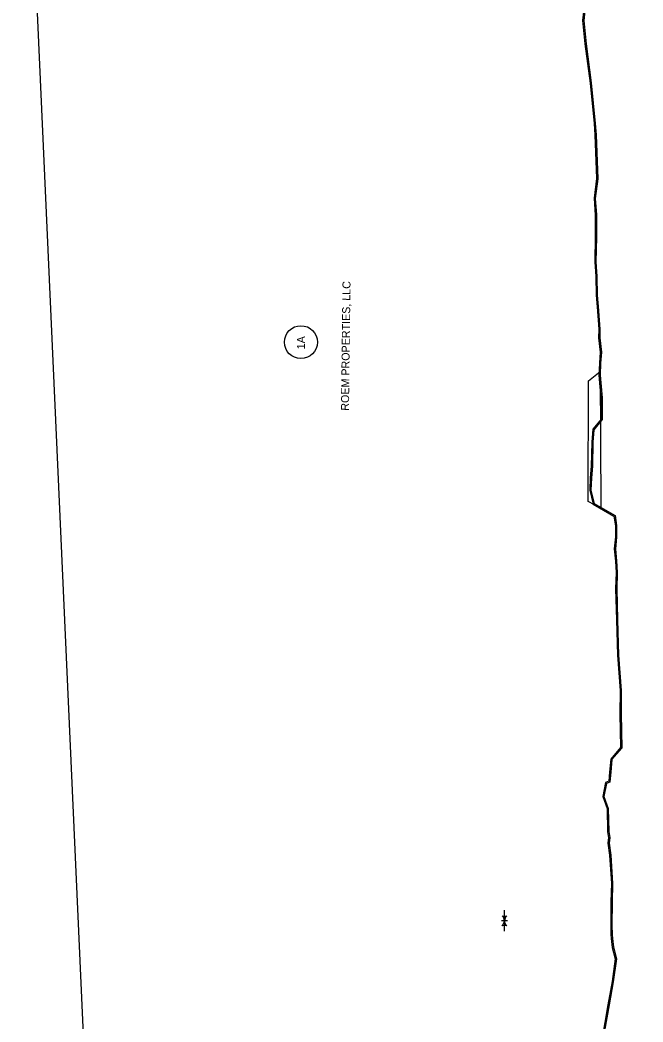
# Model space of a CAD drawing. Extents: x 20504422 to 20508365, y 7965199 to 7983597.
# Drawn here: x 20505551 to 20506611, y 7972359 to 7974062 of the extents above; entities that cross this region are included whole.
import ezdxf

# ---------------------------------------------------------------- set-up
doc = ezdxf.new("R2010")
doc.units = 0
for name, color, linetype in [('SurControl', 7, 'Continuous'), ('SurDikeDam', 7, 'Continuous'), ('SurLotCorner', 7, 'Continuous'), ('SurRipRap', 7, 'Continuous'), ('SurTopOfWater', 7, 'Continuous'), ('SurWetlands', 7, 'Continuous')]:
    doc.layers.add(name, color=color, linetype=linetype)

msp = doc.modelspace()

# ---------------------------------------------------------------- linework, layer by layer
at = {"layer": 'SurControl'}
msp.add_circle((20506029.1, 7973514.4), 28, dxfattribs=at)
at = {"layer": 'SurDikeDam'}
for p, q in [((20506518, 7973448.6), (20506537.8, 7973464.4)), ((20506537.8, 7973464.4), (20506539.1, 7973232.4)), ((20506517.4, 7973243.7), (20506518, 7973448.6)), ((20506539.1, 7973232.4), (20506517.4, 7973243.7))]:
    msp.add_line(p, q, dxfattribs=at)
at = {"layer": 'SurLotCorner'}
for p, q in [((20506375.1, 7972531.1), (20506375.3, 7972549)), ((20506380.2, 7972531), (20506370.1, 7972531.2)), ((20506375.1, 7972531.1), (20506374.9, 7972513.2))]:
    msp.add_line(p, q, dxfattribs=at)
for centre, radius, start, end in [((20506360.6, 7972529.7), 14.6, 5.3849, 43.1922), ((20506375.4, 7972550.3), 11.4, 248.6722, 289.8859), ((20506389.6, 7972529.4), 14.6, 135.366, 173.1732), ((20506360.6, 7972532.8), 14.6, 315.366, 353.1732), ((20506374.9, 7972511.9), 11.4, 68.6722, 109.8859), ((20506389.6, 7972532.5), 14.6, 185.3849, 223.1922)]:
    msp.add_arc(centre, radius, start, end, dxfattribs=at)
at = {"layer": 'SurRipRap'}
msp.add_lwpolyline([(20505692.1, 7971595), (20507690.1, 7971685.2), (20507549.3, 7974806.4), (20505551.3, 7974716.3)], close=True, dxfattribs=at)
at = {"layer": 'SurTopOfWater'}
for points in [[(20506512.3, 7974100.1), (20506508.1, 7974060.8), (20506512.1, 7974021.3), (20506520.7, 7973954.7), (20506527.7, 7973886), (20506529, 7973866.8), (20506531.8, 7973792.2), (20506527.7, 7973758.8), (20506529.5, 7973730.4), (20506529.5, 7973693.1), (20506528.7, 7973650.8), (20506530.4, 7973626.1), (20506531, 7973594.1), (20506532.8, 7973574.6), (20506535.6, 7973536.2), (20506535.2, 7973521.7), (20506538.1, 7973497.4), (20506536.7, 7973478.5), (20506535.8, 7973458.5), (20506537.5, 7973438.7), (20506539.1, 7973419.5), (20506539.4, 7973383.4), (20506525.5, 7973366.3), (20506523.8, 7973344.3), (20506522.9, 7973303.8), (20506521.1, 7973284), (20506520.2, 7973262.9), (20506525.9, 7973238.9), (20506561.4, 7973218.6), (20506564, 7973202.4), (20506564, 7973183.3), (20506562, 7973163), (20506563.8, 7973142.5), (20506565, 7973122.9), (20506564.3, 7973095.2), (20506565.6, 7973042.8), (20506567.3, 7972982.6), (20506571.7, 7972922.6), (20506571.4, 7972882.8), (20506572.6, 7972825.4), (20506556, 7972805.9), (20506553.9, 7972783.7), (20506552.7, 7972768.1), (20506546.9, 7972766), (20506542.4, 7972742.3), (20506549.7, 7972721.9), (20506550.4, 7972682.4), (20506552.3, 7972672.4), (20506551.2, 7972663.1), (20506553.9, 7972642.4), (20506557.2, 7972594.3), (20506556.3, 7972563.2), (20506555.9, 7972523), (20506556.2, 7972507.7), (20506556.8, 7972500.9), (20506558.6, 7972485.9), (20506563.4, 7972466.3), (20506558.3, 7972428), (20506551.2, 7972388.5), (20506540.5, 7972328.4)], [(20506514.4, 7974100.3), (20506510.1, 7974060.8), (20506514.1, 7974021.5), (20506522.7, 7973955), (20506529.7, 7973886.2), (20506531, 7973866.9), (20506533.8, 7973792.1), (20506529.7, 7973758.7), (20506531.5, 7973730.5), (20506531.5, 7973693), (20506530.7, 7973650.9), (20506532.4, 7973626.2), (20506533, 7973594.2), (20506534.8, 7973574.7), (20506537.6, 7973536.2), (20506537.2, 7973521.8), (20506540.1, 7973497.4), (20506538.7, 7973478.4), (20506537.8, 7973458.5), (20506539.5, 7973438.8), (20506541.1, 7973419.6), (20506541.4, 7973382.7), (20506527.4, 7973365.5), (20506525.7, 7973344.2), (20506524.9, 7973303.7), (20506523.1, 7973283.9), (20506522.2, 7973263.1), (20506527.6, 7973240.2), (20506563.2, 7973219.9), (20506566, 7973202.6), (20506566, 7973183.2), (20506564, 7973163), (20506565.8, 7973142.6), (20506567, 7973122.9), (20506566.3, 7973095.2), (20506567.6, 7973042.8), (20506569.3, 7972982.7), (20506573.7, 7972922.7), (20506573.4, 7972882.8), (20506574.6, 7972824.6), (20506557.9, 7972805.1), (20506555.9, 7972783.5), (20506554.6, 7972766.7), (20506548.7, 7972764.5), (20506544.4, 7972742.5), (20506551.7, 7972722.2), (20506552.4, 7972682.6), (20506554.3, 7972672.4), (20506553.2, 7972663.1), (20506555.9, 7972642.6), (20506559.2, 7972594.4), (20506558.3, 7972563.1), (20506557.9, 7972523), (20506558.2, 7972507.8), (20506558.8, 7972501.2), (20506560.6, 7972486.3), (20506565.5, 7972466.4), (20506560.3, 7972427.6), (20506553.2, 7972388.1), (20506542.5, 7972328.2)]]:
    msp.add_lwpolyline(points, dxfattribs=at)
at = {"layer": 'SurWetlands'}
for p, q in [((20506518, 7973448.6), (20506537.8, 7973464.4)), ((20506517.4, 7973243.7), (20506518, 7973448.6)), ((20506539.1, 7973232.4), (20506517.4, 7973243.7))]:
    msp.add_line(p, q, dxfattribs=at)

# ---------------------------------------------------------------- texts
at = {"layer": 'SurControl'}
for s, p in [('ROEM PROPERTIES, LLC', (20506110.7, 7973397.8)), ('1A', (20506035.8, 7973502.2))]:
    msp.add_text(s, height=13.6, rotation=89.2974, dxfattribs=at).set_placement(p)

doc.saveas('drawing.dxf')
